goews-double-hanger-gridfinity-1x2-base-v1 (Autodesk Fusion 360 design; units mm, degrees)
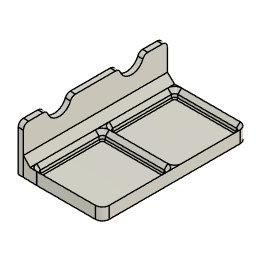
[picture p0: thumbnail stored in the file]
base_feature "Base Feature1" bodies "Double Plate Blank", "Double Plate Gridfinity 1x2"
fillet "Fillet1" radius 3
copy_paste_bodies "CutPasteBodies"
align "Align1"
align "Align2"
align "Align3"
move "Move1"
move "Move2"
copy_paste_bodies "CopyPasteBodies2"
move "Move3"
combine "Combine1" bodies "Grid"
sketch "Sketch1" plane through (0, 0, -172.1244) normal (0, 0, -1) x axis (1, 0, 0)
  line L1 (99.15, -62.8) -> (96.15, -62.8)
  line L2 (99.15, 20.8) -> (99.15, -62.8)
  line L3 (96.15, 20.8) -> (99.15, 20.8)
  line L4 (96.15, 15.3) -> (96.15, 20.8)
  line L5 (96.15, -15.3) -> (96.15, 15.3)
  line L6 (96.15, -26.7) -> (96.15, -15.3)
  line L7 (96.15, -57.3) -> (96.15, -26.7)
  line L8 (96.15, -62.8) -> (96.15, -57.3)
  line L9 (141.15, 18.1536) -> (107.15, 18.1536)
  line L10 (142.3036, -17) -> (142.3036, 17)
  line L11 (107.15, -18.1536) -> (141.15, -18.1536)
  line L12 (105.9964, 17) -> (105.9964, -17)
  line L13 (145.15, 17) -> (145.15, -17)
  line L14 (107.15, 21) -> (141.15, 21)
  line L15 (103.15, -17) -> (103.15, 17)
  line L16 (103.15, -59) -> (103.15, -25)
  line L17 (141.15, -63) -> (107.15, -63)
  line L18 (145.15, -25) -> (145.15, -59)
  line L19 (141.15, -23.8464) -> (107.15, -23.8464)
  line L20 (142.3036, -59) -> (142.3036, -25)
  line L21 (107.15, -60.1536) -> (141.15, -60.1536)
  line L22 (105.9964, -25) -> (105.9964, -59)
  line L23 (107.0494, 20.9987) -> (99.15, 20.8)
  line L24 (107.0494, -62.9987) -> (99.15, -62.8)
  arc A1 centre (107.15, 17) radius 1.1536 clockwise from (105.9964, 17) to (107.15, 18.1536)
  arc A2 centre (141.15, 17) radius 1.1536 clockwise from (141.15, 18.1536) to (142.3036, 17)
  arc A3 centre (141.15, -17) radius 1.1536 clockwise from (142.3036, -17) to (141.15, -18.1536)
  arc A4 centre (107.15, -17) radius 1.1536 clockwise from (107.15, -18.1536) to (105.9964, -17)
  arc A5 centre (141.15, -25) radius 4 clockwise from (141.15, -21) to (145.15, -25)
  arc A6 centre (141.15, -17) radius 4 clockwise from (145.15, -17) to (141.15, -21)
  arc A7 centre (141.15, 17) radius 4 clockwise from (141.15, 21) to (145.15, 17)
  arc A8 centre (107.15, 17) radius 4 clockwise from (103.15, 17) to (107.15, 21)
  arc A9 centre (107.15, -17) radius 4 clockwise from (107.15, -21) to (103.15, -17)
  arc A10 centre (107.15, -25) radius 4 clockwise from (103.15, -25) to (107.15, -21)
  arc A11 centre (107.15, -59) radius 4 clockwise from (107.15, -63) to (103.15, -59)
  arc A12 centre (141.15, -59) radius 4 clockwise from (145.15, -59) to (141.15, -63)
  arc A13 centre (107.15, -25) radius 1.1536 clockwise from (105.9964, -25) to (107.15, -23.8464)
  arc A14 centre (141.15, -25) radius 1.1536 clockwise from (141.15, -23.8464) to (142.3036, -25)
  arc A15 centre (141.15, -59) radius 1.1536 clockwise from (142.3036, -59) to (141.15, -60.1536)
  arc A16 centre (107.15, -59) radius 1.1536 clockwise from (107.15, -60.1536) to (105.9964, -59)
  point P4 (99.15, 20.8)
  point P48 (99.15, 20.8)
  point P49 (107.0494, 20.9987)
  point P3 (99.15, -62.8)
  point P50 (99.15, -62.8)
  point P51 (107.0494, -62.9987)
  coincident P4 P48
  coincident A8 P49
  tangent A8 L23
  coincident P3 P50
  coincident A11 P51
  tangent A11 L24
extrude "Extrude1" add sketch "Sketch1" profile of L2 A8 L15 A9 A10 L16 A11 L23 L24 against normal blind 4.646 bodies "Grid (1)"
chamfer "Chamfer1" distance 4
sketch "Sketch2" plane through (0, 0, -172.1244) normal (0, 0, -1) x axis (1, 0, 0)
  line L1 (141.15, -23.8464) -> (107.15, -23.8464)
  line L2 (142.3036, -59) -> (142.3036, -25)
  line L3 (107.15, -60.1536) -> (141.15, -60.1536)
  line L4 (105.9964, -25) -> (105.9964, -59)
  line L5 (141.15, 18.1536) -> (107.15, 18.1536)
  line L6 (142.3036, -17) -> (142.3036, 17)
  line L7 (107.15, -18.1536) -> (141.15, -18.1536)
  line L8 (105.9964, 17) -> (105.9964, -17)
  line L9 (99.15, -62.8) -> (96.15, -62.8)
  line L10 (107.0494, -62.9987) -> (99.15, -62.8)
  line L11 (141.15, -63) -> (107.15, -63)
  line L12 (145.15, -25) -> (145.15, -59)
  line L13 (145.15, 17) -> (145.15, -17)
  line L14 (107.15, 21) -> (141.15, 21)
  line L15 (99.15, 20.8) -> (107.0494, 20.9987)
  line L16 (96.15, 20.8) -> (99.15, 20.8)
  line L17 (96.15, 15.3) -> (96.15, 20.8)
  line L18 (96.15, -15.3) -> (96.15, 15.3)
  line L19 (96.15, -26.7) -> (96.15, -15.3)
  line L20 (96.15, -57.3) -> (96.15, -26.7)
  line L21 (96.15, -62.8) -> (96.15, -57.3)
  line L22 (145.15, -25) -> (145.15, -17)
  arc A1 centre (107.15, -25) radius 1.1536 clockwise from (105.9964, -25) to (107.15, -23.8464)
  arc A2 centre (141.15, -25) radius 1.1536 clockwise from (141.15, -23.8464) to (142.3036, -25)
  arc A3 centre (141.15, -59) radius 1.1536 clockwise from (142.3036, -59) to (141.15, -60.1536)
  arc A4 centre (107.15, -59) radius 1.1536 clockwise from (107.15, -60.1536) to (105.9964, -59)
  arc A5 centre (107.15, 17) radius 1.1536 clockwise from (105.9964, 17) to (107.15, 18.1536)
  arc A6 centre (141.15, 17) radius 1.1536 clockwise from (141.15, 18.1536) to (142.3036, 17)
  arc A7 centre (141.15, -17) radius 1.1536 clockwise from (142.3036, -17) to (141.15, -18.1536)
  arc A8 centre (107.15, -17) radius 1.1536 clockwise from (107.15, -18.1536) to (105.9964, -17)
  arc A9 centre (107.15, -59) radius 4 clockwise from (107.15, -63) to (107.0494, -62.9987)
  arc A10 centre (141.15, -59) radius 4 clockwise from (145.15, -59) to (141.15, -63)
  arc A11 centre (141.15, -25) radius 4 clockwise from (141.15, -21) to (145.15, -25)
  arc A12 centre (141.15, -17) radius 4 clockwise from (145.15, -17) to (141.15, -21)
  arc A13 centre (141.15, 17) radius 4 clockwise from (141.15, 21) to (145.15, 17)
  arc A14 centre (107.15, 17) radius 4 clockwise from (107.0494, 20.9987) to (107.15, 21)
  point P34 (145.15, -17)
  point P45 (145.15, -17)
  point P32 (145.15, -25)
  point P46 (145.15, -25)
  coincident P34 P45
  coincident P32 P46
extrude "Extrude2" add sketch "Sketch2" profile of A11 A12 L22 against normal blind 4.646
move_face "MoveFace1"
move_face "MoveFace2"
sketch "Sketch3" plane through (0, 0, -172.1244) normal (0, 0, -1) x axis (1, 0, 0)
  line L1 (141.15, -23.8464) -> (107.15, -23.8464)
  line L2 (142.3036, -59) -> (142.3036, -25)
  line L3 (107.15, -60.1536) -> (141.15, -60.1536)
  line L4 (105.9964, -25) -> (105.9964, -59)
  line L5 (141.15, 18.1536) -> (107.15, 18.1536)
  line L6 (142.3036, -17) -> (142.3036, 17)
  line L7 (107.15, -18.1536) -> (141.15, -18.1536)
  line L8 (105.9964, 17) -> (105.9964, -17)
  line L9 (99.15, -62.8) -> (96.15, -62.8)
  line L10 (107.0494, -62.9987) -> (99.15, -62.8)
  line L11 (141.15, -63) -> (107.15, -63)
  line L12 (145.15, 17) -> (145.15, -59)
  line L13 (107.15, 21) -> (141.15, 21)
  line L14 (99.15, 20.8) -> (107.0494, 20.9987)
  line L15 (96.15, 20.8) -> (99.15, 20.8)
  line L16 (96.15, 15.1) -> (96.15, 20.8)
  line L17 (96.15, -15.1) -> (96.15, 15.1)
  line L18 (96.15, -26.9) -> (96.15, -15.1)
  line L19 (96.15, -57.1) -> (96.15, -26.9)
  line L20 (96.15, -62.8) -> (96.15, -57.1)
  arc A1 centre (107.15, -25) radius 1.1536 clockwise from (105.9964, -25) to (107.15, -23.8464)
  arc A2 centre (141.15, -25) radius 1.1536 clockwise from (141.15, -23.8464) to (142.3036, -25)
  arc A3 centre (141.15, -59) radius 1.1536 clockwise from (142.3036, -59) to (141.15, -60.1536)
  arc A4 centre (107.15, -59) radius 1.1536 clockwise from (107.15, -60.1536) to (105.9964, -59)
  arc A5 centre (107.15, 17) radius 1.1536 clockwise from (105.9964, 17) to (107.15, 18.1536)
  arc A6 centre (141.15, 17) radius 1.1536 clockwise from (141.15, 18.1536) to (142.3036, 17)
  arc A7 centre (141.15, -17) radius 1.1536 clockwise from (142.3036, -17) to (141.15, -18.1536)
  arc A8 centre (107.15, -17) radius 1.1536 clockwise from (107.15, -18.1536) to (105.9964, -17)
  arc A9 centre (107.15, -59) radius 4 clockwise from (107.15, -63) to (107.0494, -62.9987)
  arc A10 centre (141.15, -59) radius 4 clockwise from (145.15, -59) to (141.15, -63)
  arc A11 centre (141.15, 17) radius 4 clockwise from (141.15, 21) to (145.15, 17)
  arc A12 centre (107.15, 17) radius 4 clockwise from (107.0494, 20.9987) to (107.15, 21)
extrude "Extrude3" add sketch "Sketch2" + "Sketch1" profile of S2:A1 S2:L9 S2:A2 S2:L10 S2:A3 S2:L11 S2:A4 S2:L12 S2:A13 S2:L19 S2:A14 S2:L20 S2:A15 S2:L21 S2:A16 S2:L22 S1:A1 S1:L1 S1:A2 S1:L2 S1:A3 S1:L3 S1:A4 S1:L4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 blind 2.354
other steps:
base_feature "Base Feature2" bodies "Grid"
base_feature "Base Feature3" bodies "Grid", "Grid (1)"
named bodies: "Double Plate Blank", "Double Plate Gridfinity 1x2", "Grid", "Grid (1)"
